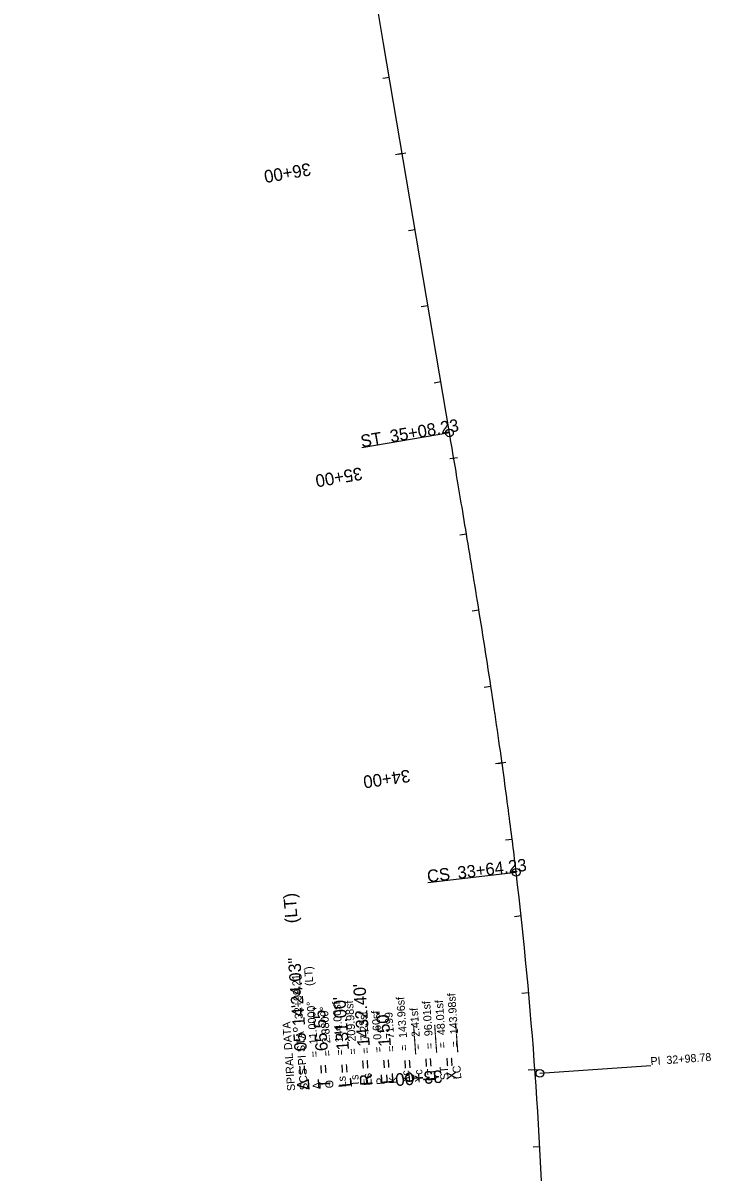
# Model space of a CAD drawing. Extents: x 21487884 to 21488802, y 8074558 to 8076894.
# Drawn here: x 21487989.1 to 21488211.8, y 8074930.5 to 8075302.7 of the extents above; entities that cross this region are included whole.
import ezdxf

# ---------------------------------------------------------------- set-up
doc = ezdxf.new("R2010")
doc.units = 0
for name, color, linetype in [('Default', 7, 'Continuous'), ('PS_BOLT', 7, 'Continuous'), ('PS_DIM', 7, 'Continuous'), ('PS_MID', 7, 'Continuous'), ('PS_SHAPE', 7, 'Continuous')]:
    doc.layers.add(name, color=color, linetype=linetype)

msp = doc.modelspace()

# ---------------------------------------------------------------- linework, layer by layer
at = {"layer": 'Default'}
msp.add_line((21488127.15, 8075169.89), (21488105.84, 8075296.07), dxfattribs=at)
msp.add_arc((21486726.15, 8074860.23), 1432.4, 1.46747, 6.70748, dxfattribs=at)
msp.add_open_spline([(21488148.75, 8075027.54), (21488148.05, 8075033.5), (21488146.57, 8075045.41), (21488143.36, 8075069.19), (21488138.92, 8075098.86), (21488134.11, 8075128.47), (21488130.15, 8075152.14), (21488128.15, 8075163.98), (21488127.15, 8075169.89)], degree=3, dxfattribs=at)
at = {"layer": 'PS_BOLT'}
for p, q in [((21488111.87, 8075260.38), (21488109.71, 8075260.02)), ((21488127.31, 8075161.57), (21488129.73, 8075161.98)), ((21488144.17, 8075063.01), (21488142, 8075062.71)), ((21488154.82, 8074963.6), (21488152.64, 8074963.44))]:
    msp.add_line(p, q, dxfattribs=at)
at = {"layer": 'PS_DIM'}
for p, q in [((21488127.15, 8075169.89), (21488098.75, 8075165.1)), ((21488148.75, 8075027.54), (21488120.15, 8075024.17)), ((21488148.75, 8075027.54), (21488120.15, 8075024.17)), ((21488156.41, 8074962.44), (21488192.31, 8074965.01))]:
    msp.add_line(p, q, dxfattribs=at)
for centre in [(21488127.15, 8075169.89), (21488148.75, 8075027.54), (21488148.75, 8075027.54), (21488156.41, 8074962.44)]:
    msp.add_circle(centre, 1.25, dxfattribs=at)
at = {"layer": 'PS_MID'}
for p, q in [((21488107.7, 8075285.03), (21488105.55, 8075284.67)), ((21488110.66, 8075260.18), (21488113.07, 8075260.58)), ((21488116.03, 8075235.73), (21488113.88, 8075235.37)), ((21488120.19, 8075211.08), (21488118.04, 8075210.71)), ((21488124.36, 8075186.43), (21488122.2, 8075186.06)), ((21488127.31, 8075161.57), (21488129.73, 8075161.98)), ((21488132.66, 8075137.12), (21488130.5, 8075136.76)), ((21488136.69, 8075112.45), (21488134.54, 8075112.1)), ((21488140.55, 8075087.75), (21488138.39, 8075087.42)), ((21488142.95, 8075062.84), (21488145.38, 8075063.18)), ((21488147.45, 8075038.23), (21488145.29, 8075037.96)), ((21488150.34, 8075013.4), (21488148.17, 8075013.16)), ((21488152.8, 8074988.52), (21488150.62, 8074988.32)), ((21488153.6, 8074963.51), (21488156.04, 8074963.69)), ((21488156.41, 8074938.65), (21488154.23, 8074938.53))]:
    msp.add_line(p, q, dxfattribs=at)
at = {"layer": 'PS_SHAPE'}
for p, q in [((21488105.84, 8075296.07), (21487989.11, 8075987.15)), ((21488105.84, 8075296.07), (21487989.11, 8075987.15)), ((21488127.15, 8075169.89), (21488105.84, 8075296.07)), ((21488127.15, 8075169.89), (21488105.84, 8075296.07))]:
    msp.add_line(p, q, dxfattribs=at)
msp.add_arc((21486726.15, 8074860.23), 1432.4, 1.46747, 6.70748, dxfattribs=at)
msp.add_arc((21486726.15, 8074860.23), 1432.4, 1.46747, 6.70748, dxfattribs=at)
msp.add_open_spline([(21488148.75, 8075027.54), (21488148.05, 8075033.5), (21488146.57, 8075045.41), (21488143.36, 8075069.19), (21488138.92, 8075098.86), (21488134.11, 8075128.47), (21488130.15, 8075152.14), (21488128.15, 8075163.98), (21488127.15, 8075169.89)], degree=3, dxfattribs=at)
msp.add_open_spline([(21488148.75, 8075027.54), (21488148.05, 8075033.5), (21488146.57, 8075045.41), (21488143.36, 8075069.19), (21488138.92, 8075098.86), (21488134.11, 8075128.47), (21488130.15, 8075152.14), (21488128.15, 8075163.98), (21488127.15, 8075169.89)], degree=3, dxfattribs=at)

# ---------------------------------------------------------------- texts
at = {"layer": 'PS_BOLT'}
msp.add_text('35+00', height=4.08, rotation=189.5781, dxfattribs=at).set_placement((21488098.6, 8075158.8))
at = {"layer": 'PS_DIM'}
for s, height, rotation, p in [('35+08.23', 4.008, 9.5875, (21488108.23, 8075166.78)), ('ST', 4.008, 9.5875, (21488098.74, 8075165.17)), ('33+64.23', 4.008, 6.7075, (21488129.98, 8075025.41)), ('33+64.23', 4.008, 6.7075, (21488129.98, 8075025.41)), ('CS', 4.008, 6.7075, (21488120.14, 8075024.25)), ('CS', 4.008, 6.7075, (21488120.14, 8075024.25)), (' (LT)', 4.008, 94.0875, (21488078.15, 8075009.68)), ('05°14\'24.03"', 4.008, 94.0875, (21488081, 8074969.78)), ('32+99.21', 2.592, 94.0875, (21488079.72, 8074980.13)), (' (LT)', 2.592, 94.0875, (21488083.18, 8074989.86)), ("1432.40'", 4.008, 94.0875, (21488101.39, 8074971.21)), ("131.00'", 4.008, 94.0875, (21488094.65, 8074970)), ('143.96sf', 2.592, 94.0875, (21488113.42, 8074973.99)), ('143.98sf', 2.592, 94.0875, (21488129.96, 8074975.17)), ('11.0000°', 2.592, 94.0875, (21488084.46, 8074971.92)), ("65.55'", 4.008, 94.0875, (21488087.83, 8074969.76)), ('2.8800°', 2.592, 94.0875, (21488088.6, 8074972.22)), ('144.00sf', 2.592, 94.0875, (21488092.73, 8074972.51)), ('209.98sf', 2.592, 94.0875, (21488096.87, 8074972.81)), ('0.60sf', 2.592, 94.0875, (21488105.14, 8074973.4)), ('2.41sf', 2.592, 94.0875, (21488117.55, 8074974.29)), ('96.01sf', 2.592, 94.0875, (21488121.69, 8074974.58)), ('48.01sf', 2.592, 94.0875, (21488125.83, 8074974.88)), ('SPIRAL DATA', 2.592, 94.0875, (21488077.23, 8074956.78)), ('7.23sf', 2.592, 94.0875, (21488101.01, 8074973.11)), ("1.50'", 4.008, 94.0875, (21488108.22, 8074971.22)), ('71.99', 2.592, 94.0875, (21488109.28, 8074973.7)), ('SCS PI STA ', 2.592, 94.0875, (21488081.36, 8074957.08)), ('e = ___ ', 4.008, 94.0875, (21488115.89, 8074959.55)), ('L = ___', 4.008, 94.0875, (21488122.68, 8074960.03)), ('x = ___', 4.008, 94.0875, (21488129.48, 8074960.52)), ('= ', 2.592, 94.0875, (21488113.72, 8074969.79)), ('= ', 2.592, 94.0875, (21488117.85, 8074970.08)), ('= ', 2.592, 94.0875, (21488121.99, 8074970.38)), ('= ', 2.592, 94.0875, (21488126.13, 8074970.67)), ('= ', 2.592, 94.0875, (21488130.26, 8074970.97)), ('= ', 2.592, 94.0875, (21488084.76, 8074967.72)), ('= ', 2.592, 94.0875, (21488088.9, 8074968.01)), ('= ', 2.592, 94.0875, (21488093.03, 8074968.31)), ('= ', 2.592, 94.0875, (21488097.17, 8074968.6)), ('= ', 2.592, 94.0875, (21488101.31, 8074968.9)), ('= ', 2.592, 94.0875, (21488105.44, 8074969.19)), ('= ', 2.592, 94.0875, (21488109.58, 8074969.49)), ('PI ', 2.592, 4.0875, (21488192.31, 8074965.06)), ('32+98.78', 2.592, 4.0875, (21488197.46, 8074965.43)), ('Δ = ', 4.008, 94.0875, (21488081.9, 8074957.12)), ('T = ', 4.008, 94.0875, (21488088.7, 8074957.6)), ('L = ', 4.008, 94.0875, (21488095.5, 8074958.09)), ('R = ', 4.008, 94.0875, (21488102.29, 8074958.57)), ('E = ', 4.008, 94.0875, (21488109.09, 8074959.06)), ('ST ', 2.592, 94.0875, (21488126.87, 8074960.33)), ('LC', 2.592, 94.0875, (21488131, 8074960.63)), ('Ls', 2.592, 94.0875, (21488093.77, 8074957.97)), ('Ts', 2.592, 94.0875, (21488097.91, 8074958.26)), ('Es', 2.592, 94.0875, (21488102.05, 8074958.56)), ('P', 2.59, 94.0875, (21488106.18, 8074958.85)), ('K', 2.59, 94.0875, (21488110.32, 8074959.15)), ('Xc', 2.592, 94.0875, (21488114.46, 8074959.44)), ('Yc', 2.592, 94.0875, (21488118.59, 8074959.74)), ('LT', 2.592, 94.0875, (21488122.73, 8074960.03)), ('Δ', 2.59, 94.0875, (21488085.5, 8074957.37)), ('Θ ', 2.592, 94.0875, (21488089.64, 8074957.67))]:
    msp.add_text(s, height=height, rotation=rotation, dxfattribs=at).set_placement(p)
at = {"layer": 'PS_MID'}
for s, rotation, p in [('36+00', 189.5875, (21488081.95, 8075257.4)), ('35+00', 189.5781, (21488098.6, 8075158.8)), ('34+00', 187.9605, (21488114.17, 8075060.88)), ('33+00', 184.1382, (21488124.75, 8074963.47))]:
    msp.add_text(s, height=4.08, rotation=rotation, dxfattribs=at).set_placement(p)

doc.saveas('drawing.dxf')
